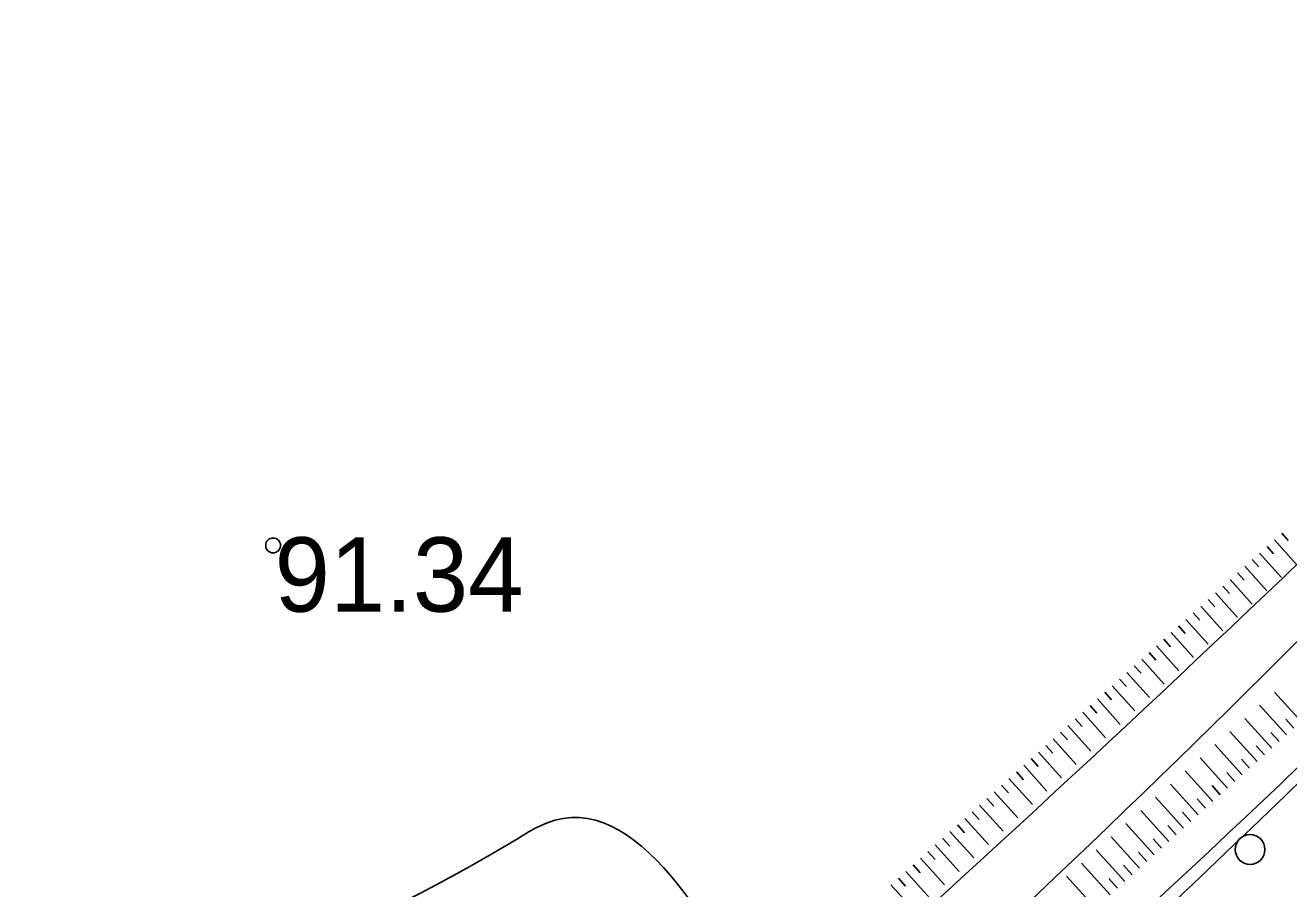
# Model space of a CAD drawing. Extents: x 316000 to 728450, y 314368 to 726000.
# Drawn here: x 725638.8 to 725702.4, y 315596.5 to 315640.1 of the extents above; entities that cross this region are included whole.
import ezdxf

# ---------------------------------------------------------------- set-up
doc = ezdxf.new("R2010")
doc.units = 0
for name, color, linetype in [('HIDG_GRAV_####_####_#', 7, 'Continuous'), ('RELJ_AATZ_####_TKST_#', 7, 'Continuous'), ('RELJ_ELEM_####_####_#', 7, 'Continuous'), ('RELJ_NOGA_####_####_#', 7, 'Continuous'), ('TERT_ELEM_####_####_#', 7, 'Continuous'), ('TERT_KONT_####_####_#', 7, 'Continuous')]:
    doc.layers.add(name, color=color, linetype=linetype)

msp = doc.modelspace()

# ---------------------------------------------------------------- linework, layer by layer
at = {"layer": 'HIDG_GRAV_####_####_#'}
for points in [[(725743.944, 315631.872), (725731.1800000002, 315638.5140000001), (725730.0588248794, 315638.4860084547), (725729.0416291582, 315637.5281018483), (725728.0741186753, 315636.1890738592), (725727.1019992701, 315635.017718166), (725611.6787771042, 315529.82054677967)], [(725741.1610000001, 315628.109), (725732.013, 315633.48000000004), (725729.3674430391, 315630.93907173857), (725612.6699933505, 315527.51301727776), (725555.2138402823, 315474.3075427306)]]:
    msp.add_spline(points, degree=3, dxfattribs=at)
at = {"layer": 'RELJ_ELEM_####_####_#'}
msp.add_circle((725651.2473051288, 315613.8291355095), 0.375, dxfattribs=at)
at = {"layer": 'RELJ_NOGA_####_####_#'}
for p, q in [((725702.09835772, 315614.45099404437), (725702.4278188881, 315614.0847587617)), ((725701.3549115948, 315613.7821982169), (725701.6856753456, 315613.41451495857)), ((725701.7266346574, 315614.1165961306), (725702.8270095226, 315612.89339856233)), ((725700.9831885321, 315613.44780030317), (725702.0879053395, 315612.21977614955)), ((725700.2397424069, 315612.7790044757), (725701.3488011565, 315611.54615373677)), ((725700.6114654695, 315613.1134023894), (725700.9435318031, 315612.7442711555)), ((725699.4962962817, 315612.1102086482), (725700.6096969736, 315610.8725313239)), ((725699.8680193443, 315612.4446065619), (725700.2013882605, 315612.07402735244)), ((725698.7528501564, 315611.44141282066), (725699.8705927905, 315610.1989089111)), ((725699.1245732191, 315611.77581073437), (725699.459244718, 315611.4037835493)), ((725698.0094040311, 315610.77261699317), (725699.1314886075, 315609.52528649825)), ((725698.3811270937, 315611.1070149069), (725698.7171011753, 315610.7335397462)), ((725697.2659579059, 315610.1038211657), (725698.3923844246, 315608.8516640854)), ((725697.6376809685, 315610.4382190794), (725697.9749576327, 315610.06329594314)), ((725696.5225117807, 315609.4350253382), (725697.6532802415, 315608.1780416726)), ((725696.8942348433, 315609.7694232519), (725697.2328140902, 315609.3930521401)), ((725695.7790656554, 315608.76622951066), (725696.9141760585, 315607.5044192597)), ((725696.150788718, 315609.10062742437), (725696.4906705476, 315608.72280833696)), ((725695.0356195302, 315608.0974336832), (725696.1750718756, 315606.830796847)), ((725695.4073425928, 315608.43183159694), (725695.7485270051, 315608.0525645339)), ((725694.2921734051, 315607.4286378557), (725695.4359676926, 315606.15717443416)), ((725694.6638964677, 315607.76303576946), (725695.0063834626, 315607.3823207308)), ((725693.9204503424, 315607.094239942), (725694.26423992, 315606.71207692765)), ((725693.1770042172, 315606.42544411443), (725693.5220963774, 315606.04183312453)), ((725693.5487272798, 315606.7598420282), (725694.6968635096, 315605.4835520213)), ((725703.0707787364, 315604.95687764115), (725701.7246747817, 315606.4399720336)), ((725692.4335580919, 315605.75664828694), (725692.7799528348, 315605.37158932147)), ((725692.8052811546, 315606.09104620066), (725693.9577593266, 315604.8099296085)), ((725702.330301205, 315604.28479652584), (725700.9762425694, 315605.776655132)), ((725691.6901119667, 315605.08785245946), (725692.0378092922, 315604.70134551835)), ((725692.0618350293, 315605.4222503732), (725693.2186551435, 315604.13630719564)), ((725701.5898236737, 315603.61271541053), (725700.227810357, 315605.1133382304)), ((725702.7005399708, 315604.6208370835), (725702.2955155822, 315605.0670800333)), ((725690.9466658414, 315604.419056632), (725691.2956657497, 315604.0311017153)), ((725691.318388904, 315604.7534545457), (725692.4795509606, 315603.4626847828)), ((725700.8493461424, 315602.9406342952), (725699.4793781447, 315604.4500213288)), ((725701.9600624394, 315603.9487559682), (725701.5526516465, 315604.3976281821)), ((725690.2032197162, 315603.75026080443), (725690.5535222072, 315603.36085791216)), ((725690.5749427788, 315604.0846587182), (725691.7404467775, 315602.78906236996)), ((725700.108868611, 315602.2685531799), (725698.7309459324, 315603.7867044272)), ((725701.219584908, 315603.2766748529), (725700.8097877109, 315603.72817633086)), ((725689.459773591, 315603.08146497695), (725689.8113786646, 315602.6906141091)), ((725689.8314966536, 315603.41586289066), (725691.0013425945, 315602.1154399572)), ((725699.3683910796, 315601.5964720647), (725697.98251372, 315603.1233875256)), ((725700.4791073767, 315602.6045937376), (725700.0669237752, 315603.0587244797)), ((725688.7163274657, 315602.41266914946), (725689.0692351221, 315602.02037030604)), ((725689.0880505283, 315602.74706706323), (725690.2622384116, 315601.44181754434)), ((725698.6279135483, 315600.92439094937), (725697.2340815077, 315602.46007062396)), ((725699.7386298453, 315601.93251262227), (725699.3240598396, 315602.3892726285)), ((725687.9728813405, 315601.743873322), (725688.3270915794, 315601.3501265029)), ((725688.3446044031, 315602.07827123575), (725689.5231342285, 315600.76819513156)), ((725697.8874360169, 315600.252309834), (725696.4856492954, 315601.7967537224)), ((725698.998152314, 315601.26043150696), (725698.581195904, 315601.71982077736)), ((725687.2294352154, 315601.07507749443), (725687.5849480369, 315600.6798826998)), ((725687.601158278, 315601.40947540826), (725688.7840300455, 315600.0945727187)), ((725697.1469584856, 315599.5802287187), (725695.7372170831, 315601.1334368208)), ((725698.2576747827, 315600.5883503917), (725697.8383319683, 315601.05036892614)), ((725686.48598909, 315600.40628166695), (725686.8428044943, 315600.00963889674)), ((725686.8577121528, 315600.7406795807), (725688.0449258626, 315599.4209503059)), ((725696.4064809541, 315598.90814760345), (725694.9887848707, 315600.47011991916)), ((725686.1142660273, 315600.07188375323), (725687.3058216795, 315598.74732789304)), ((725695.6660034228, 315598.23606648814), (725694.2403526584, 315599.8068030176)), ((725697.5171972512, 315599.9162692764), (725697.0954680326, 315600.3809170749)), ((725685.3708199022, 315599.40308792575), (725686.5667174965, 315598.0737054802)), ((725685.7425429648, 315599.73748583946), (725686.1006609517, 315599.3393950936)), ((725694.9255258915, 315597.56398537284), (725693.4919204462, 315599.143486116)), ((725696.7767197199, 315599.2441881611), (725696.3526040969, 315599.71146522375)), ((725684.627373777, 315598.73429209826), (725685.8276133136, 315597.4000830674)), ((725684.9990968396, 315599.068690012), (725685.3585174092, 315598.66915129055)), ((725696.0362421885, 315598.5721070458), (725695.6097401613, 315599.0420133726)), ((725683.8839276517, 315598.0654962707), (725685.0885091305, 315596.7264606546)), ((725684.2556507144, 315598.39989418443), (725684.6163738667, 315597.99890748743)), ((725694.1850483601, 315596.8919042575), (725692.7434882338, 315598.4801692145)), ((725695.2957646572, 315597.9000259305), (725694.8668762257, 315598.3725615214)), ((725683.1404815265, 315597.39670044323), (725684.3494049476, 315596.05283824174)), ((725683.5122045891, 315597.731098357), (725683.874230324, 315597.3286636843)), ((725693.4445708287, 315596.2198231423), (725691.9950560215, 315597.8168523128)), ((725694.5552871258, 315597.2279448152), (725694.1240122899, 315597.7031096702)), ((725682.3970354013, 315596.72790461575), (725683.6103007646, 315595.3792158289)), ((725682.7687584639, 315597.0623025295), (725683.1320867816, 315596.65841988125)), ((725692.7040932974, 315595.547742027), (725691.2466238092, 315597.1535354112)), ((725693.8148095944, 315596.5558636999), (725693.3811483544, 315597.033657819))]:
    msp.add_line(p, q, dxfattribs=at)
for points in [[(725744.701, 315632.911), (725731.2122469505, 315640.0386943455), (725729.056271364, 315639.5840256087), (725728.3072907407, 315638.79600724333), (725727.6980921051, 315637.94217499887), (725727.1090350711, 315637.09598736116), (725726.4204792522, 315636.33090281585), (725610.4090988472, 315531.96836123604)], [(725740.8620000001, 315626.984), (725732.496455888, 315631.1419358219), (725731.675729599, 315631.1475109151), (725730.9005735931, 315630.5492934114), (725730.162049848, 315629.6870659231), (725729.4512203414, 315628.90061106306), (725614.9961785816, 315525.0175506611)]]:
    msp.add_spline(points, degree=3, dxfattribs=at)
at = {"layer": 'TERT_ELEM_####_####_#'}
msp.add_circle((725700.5, 315598.5), 0.75, dxfattribs=at)
at = {"layer": 'TERT_KONT_####_####_#'}
msp.add_spline([(725558.0731425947, 315596.3970132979), (725580.659, 315581.819), (725609.8680328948, 315563.59752923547), (725611.239, 315562.656), (725613.5676467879, 315564.9148792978), (725663.6488964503, 315599.09665422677), (725664.6070000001, 315599.647), (725676.5716713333, 315588.96418172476)], degree=3, dxfattribs=at)

# ---------------------------------------------------------------- texts
at = {"layer": 'RELJ_AATZ_####_TKST_#'}
msp.add_text('91.34', height=3.75, dxfattribs=at).set_placement((725651.3230000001, 315610.49))

doc.saveas('drawing.dxf')
